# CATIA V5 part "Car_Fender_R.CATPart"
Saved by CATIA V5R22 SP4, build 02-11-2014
Part number: Car_Fender_R
Material "ｱﾙﾐﾆｳﾑ": density 2710 kg/m3, Young's modulus 7e+10 Pa, Poisson ratio 0.346, thermal expansion 2.36e-05 1/K
Bounding box of the stored display mesh (mm): x -800 to 0, y -122.298 to 40, z 0 to 580
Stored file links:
  C:\DATA\Car_ASSY\教育モデル\5_ASM\FIN\Car_Fender_R.CATPart
  C:\DATA\Car_ASSY\教育モデル\5_ASM\FIN\Car_Fender.CATPart
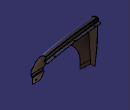
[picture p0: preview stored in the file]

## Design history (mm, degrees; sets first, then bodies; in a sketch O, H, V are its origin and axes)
Body1 (main body)
  Body2 "ｵﾘｼﾞﾅﾙ ﾊﾟｰﾂ ﾎﾞﾃﾞｨｰからのﾎﾞﾃﾞｨｰ"
    Solid1: linked copy from another document
  Assemble1: tool Body2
